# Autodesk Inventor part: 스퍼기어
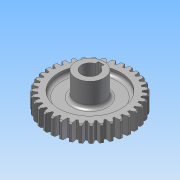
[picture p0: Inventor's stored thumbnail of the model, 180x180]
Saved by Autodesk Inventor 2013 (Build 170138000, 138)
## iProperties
Created: 2013-08
Part Number: 스퍼기어
Material: 강
Document SubType Name: Modeling
Designer: 한국산업디자인학원
Categories: <?xml version="1.0" encoding="UTF-16"?> <MemberInstance><Categories><FamilyTemplate><FamilyTemplateParameter ValueType="xs:double" Id="1" ObjectReferenceKey="da
Density: 1 g/cm^3
CustomPartVersion: 1
Author: 한국산업디자인학원
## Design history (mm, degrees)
sketch "Sketch1"
  geometry: C1 r 37 at (0, 0)
  constraints: 1 centre point
  dimensions: "d0" = 74 diameter of C1 (= da_da)
extrude "Extrusion1" new body sketch "Sketch1" distance "d1" = 15 (= da_b); taper "d2" = 0 deg
chamfer "모따기1" distance "d49" = 1; stored, may be unused: second distance "d50" = 2, angle "d51" = 45 deg
workplane "Work Plane2"
feature "피치 지름" dims "d4" = 10, "d5" = 0
workplane "Work Plane8"
workplane "Work Plane9"
sketch "스케치3"
  geometry: C1 r 36 at (0, 0) reference; C2 r 27.5 at (0, 0); C3 r 12.5 at (0, 0)
  constraints: 2 centre point, 2 coincident
  dimensions: "d52" = 55 diameter of C2; "d54" = 25 diameter of C3
extrude "돌출2" cut sketch "스케치3" distance "d55" = 5; taper "d56" = 0 deg
sketch "스케치4"
  geometry: C1 r 36 at (0, 0) reference; C2 r 27.5 at (0, 0); C3 r 12.5 at (0, 0)
  constraints: 2 centre point, 2 coincident
  dimensions: "d57" = 55 diameter of C2; "d59" = 25 diameter of C3
extrude "돌출3" cut sketch "스케치4" distance "d60" = 5; taper "d61" = 0 deg
node "작업 평면11"
sketch "스케치6"
  geometry: C1 r 12.5 at (0, 0) reference; 1 further point
extrude "돌출5" join sketch "스케치6" stored distance "d78" = 5; taper "d79" = 0 deg
hole "구멍1" diameter "d64" = 15; stored, may be unused: countersink angle "d68" = 90 deg, drill point angle "d70" = 118 deg; dims "d62" = 10, "d63" = 10, "d65" = 6, "d66" = 4, "d67" = 2, "d69" = 8
hole "구멍2" diameter "d82" = 15; stored, may be unused: countersink angle "d86" = 90 deg, drill point angle "d88" = 118 deg; dims "d80" = 10, "d81" = 10, "d83" = 6, "d84" = 4, "d85" = 2, "d87" = 8
sketch "스케치8"
  geometry: L1 (-2.5, 10)-(2.5, 10); L2 (2.5, 10)-(2.5, 7.083); L3 (2.5, 7.083)-(-2.5, 7.083); L4 (-2.5, 7.083)-(-2.5, 10); C1 r 7.5 at (0, 0) reference; 1 further point
  constraints: 8 end point, 2 parallel, 1 horizontal, 1 midpoint, 1 perpendicular, 1 vertical alignment
  dimensions: "d89" = 5 distance of L1.start L1.end; "d91" = 17.5 dimension on C1 L1
extrude "돌출6" cut sketch "스케치8" stored distance "d92" = 5; taper "d93" = 0 deg
feature "스퍼 기어" dims "da_b" = 15, "da_d" = 70, "da_aw" = 70, "da_da" = 74, "da_df" = 65, "da_dw" = 70, angle "da_beta" = 0 deg, "da_lefttooth" = 0, "da_righttooth" = 0
fillet "모깎기1" dims "d76" = 3
body "Solid1"
sketch "Sketch2"
  geometry: C1 r 37 at (0, 0) reference; C2 r 35 at (0, 0)
  constraints: 1 centre point, 1 coincident
  dimensions: "d3" = 70 diameter of C2 (= da_dw)
body "Srf1"
node "투영된 루프1"
other parameters: "d17" = 0, "d34" = 0.8976 (computed from da_z), "d39" = 0, "d41" = 0, "d47" = 0, "d48" = 0, "d77" = 31
